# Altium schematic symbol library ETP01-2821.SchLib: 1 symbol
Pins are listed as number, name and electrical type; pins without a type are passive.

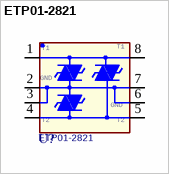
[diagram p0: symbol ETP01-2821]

## ETP01-2821
designator U?
footprint ST_SO8
pins: 1 T1, 2 GND, 3 GND1, 4 T2, 5 T2+, 6 GND2, 7 GND3, 8 T1+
